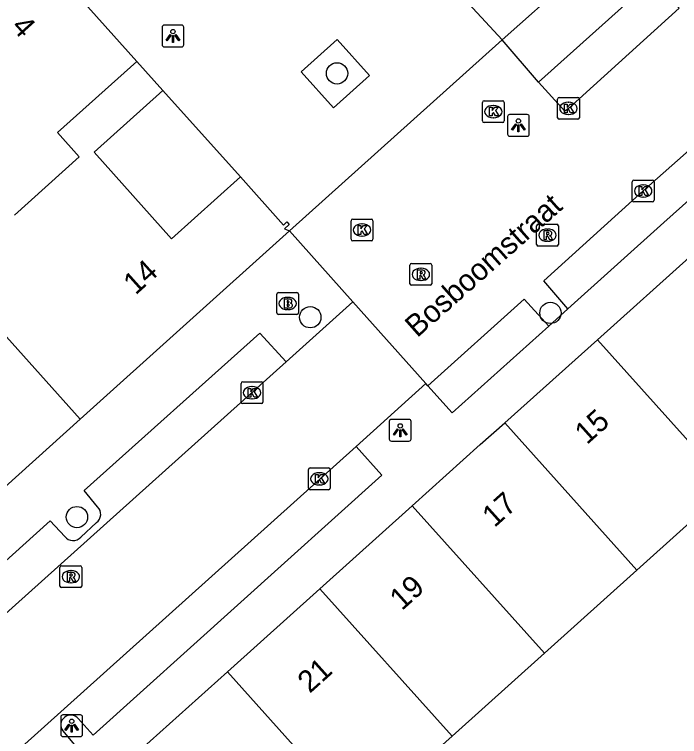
# Model space of a CAD drawing. Extents: x 162172 to 163187, y 382874 to 383684.
# Drawn here: x 162844.4 to 162874.91, y 383502.39 to 383535.51 of the extents above; entities that cross this region are included whole.
import ezdxf

# ---------------------------------------------------------------- set-up
doc = ezdxf.new("R2010")
doc.units = 0
for name, color, linetype in [('IMGEO_Boom', 7, 'Continuous'), ('IMGEO_Brandkraan', 7, 'Continuous'), ('IMGEO_Kolk', 7, 'Continuous'), ('IMGEO_Lichtpunt', 7, 'Continuous'), ('IMGEO_Muur', 7, 'Continuous'), ('IMGEO_Openbare_ruimte_label', 7, 'Continuous'), ('IMGEO_Pand', 7, 'Continuous'), ('IMGEO_Pand_nummerreeks', 7, 'Continuous'), ('IMGEO_Rijbaan_lokaal_open', 7, 'Continuous'), ('IMGEO_Rioolput', 7, 'Continuous'), ('IMGEO_Voetpad_open', 7, 'Continuous')]:
    doc.layers.add(name, color=color, linetype=linetype)

msp = doc.modelspace()

# ---------------------------------------------------------------- linework, layer by layer
at = {"layer": 'IMGEO_Boom'}
for centre in [(162859.201, 383532.804), (162868.991, 383521.821), (162857.974, 383521.623), (162847.27, 383512.456)]:
    msp.add_circle(centre, 0.489, dxfattribs=at)
at = {"layer": 'IMGEO_Brandkraan'}
for p, q in [((162856.435, 383521.824), (162856.435, 383522.676)), ((162856.51, 383522.75), (162857.362, 383522.75)), ((162856.923, 383522.53), (162856.948, 383522.53)), ((162857.436, 383522.676), (162857.436, 383521.824)), ((162856.946, 383521.97), (162856.921, 383521.97)), ((162857.362, 383521.75), (162856.51, 383521.75))]:
    msp.add_line(p, q, dxfattribs=at)
for points in [[(162856.435, 383521.824), (162856.435, 383522.676)], [(162856.51, 383522.75), (162857.362, 383522.75)], [(162857.436, 383522.676), (162857.436, 383521.824)], [(162856.783, 383522.45), (162856.783, 383522.05), (162856.996, 383522.05)], [(162857.014, 383522.45), (162856.783, 383522.45)], [(162856.962, 383522.369), (162856.908, 383522.369), (162856.908, 383522.293)], [(162856.908, 383522.293), (162856.961, 383522.293)], [(162856.97, 383522.217), (162856.908, 383522.217), (162856.908, 383522.136)], [(162856.908, 383522.136), (162856.97, 383522.136)], [(162857.362, 383521.75), (162856.51, 383521.75)]]:
    msp.add_lwpolyline(points, dxfattribs=at)
for centre, radius, start, end in [((162856.512, 383522.674), 0.0765, 91.552, 178.448), ((162856.512, 383522.674), 0.0765, 91.552, 178.448), ((162857.36, 383522.674), 0.0765, 1.552, 88.448), ((162857.36, 383522.674), 0.0765, 1.552, 88.448), ((162856.963, 383522.331), 0.0379, 267.8285, 90.9355), ((162856.971, 383522.176), 0.0404, 269.8759, 90.5077), ((162857.018, 383522.305), 0.145, 59.4692, 91.5367), ((162857.043, 383522.352), 0.0922, 285.5137, 58.1501), ((162857.048, 383522.16), 0.105, 301.3115, 78.989), ((162856.512, 383521.826), 0.0765, 181.552, 268.448), ((162856.512, 383521.826), 0.0765, 181.552, 268.448), ((162857.002, 383522.301), 0.251, 268.6676, 293.5347), ((162857.36, 383521.826), 0.0765, 271.552, 358.448), ((162857.36, 383521.826), 0.0765, 271.552, 358.448)]:
    msp.add_arc(centre, radius, start, end, dxfattribs=at)
for centre, major_axis, ratio, start_param, end_param in [((162856.922, 383522.25), (-0.387, 0.002), 0.722429, 4.712389, 7.853982), ((162856.947, 383522.25), (-0.39, 0.002), 0.717154, 1.570796, 4.712389)]:
    msp.add_ellipse(centre, major_axis=major_axis, ratio=ratio, start_param=start_param, end_param=end_param, dxfattribs=at)
at = {"layer": 'IMGEO_Kolk'}
for p, q in [((162865.872, 383530.623), (162865.872, 383531.475)), ((162865.947, 383531.549), (162866.799, 383531.549)), ((162866.873, 383531.475), (162866.873, 383530.623)), ((162869.315, 383530.771), (162869.315, 383531.623)), ((162869.39, 383531.697), (162870.242, 383531.697)), ((162869.803, 383531.477), (162869.828, 383531.477)), ((162870.316, 383531.623), (162870.316, 383530.771)), ((162866.36, 383531.329), (162866.385, 383531.329)), ((162866.383, 383530.769), (162866.358, 383530.769)), ((162869.826, 383530.917), (162869.801, 383530.917)), ((162866.799, 383530.549), (162865.947, 383530.549)), ((162870.242, 383530.697), (162869.39, 383530.697)), ((162872.746, 383526.984), (162872.746, 383527.836)), ((162872.821, 383527.91), (162873.673, 383527.91)), ((162873.747, 383527.836), (162873.747, 383526.984)), ((162873.234, 383527.69), (162873.259, 383527.69)), ((162873.257, 383527.13), (162873.232, 383527.13)), ((162873.673, 383526.91), (162872.821, 383526.91)), ((162859.849, 383525.195), (162859.849, 383526.047)), ((162859.924, 383526.121), (162860.776, 383526.121)), ((162860.337, 383525.901), (162860.362, 383525.901)), ((162860.85, 383526.047), (162860.85, 383525.195)), ((162860.36, 383525.341), (162860.335, 383525.341)), ((162860.776, 383525.121), (162859.924, 383525.121)), ((162854.803, 383517.733), (162854.803, 383518.585)), ((162854.878, 383518.659), (162855.73, 383518.659)), ((162855.804, 383518.585), (162855.804, 383517.733)), ((162855.291, 383518.439), (162855.316, 383518.439)), ((162855.314, 383517.879), (162855.289, 383517.879)), ((162855.73, 383517.659), (162854.878, 383517.659)), ((162857.889, 383513.785), (162857.889, 383514.637)), ((162857.964, 383514.711), (162858.816, 383514.711)), ((162858.89, 383514.637), (162858.89, 383513.785)), ((162858.377, 383514.491), (162858.402, 383514.491)), ((162858.4, 383513.931), (162858.375, 383513.931)), ((162858.816, 383513.711), (162857.964, 383513.711))]:
    msp.add_line(p, q, dxfattribs=at)
for points in [[(162865.872, 383530.623), (162865.872, 383531.475)], [(162865.947, 383531.549), (162866.799, 383531.549)], [(162866.873, 383531.475), (162866.873, 383530.623)], [(162869.315, 383530.771), (162869.315, 383531.623)], [(162869.39, 383531.697), (162870.242, 383531.697)], [(162870.316, 383531.623), (162870.316, 383530.771)], [(162866.193, 383531.249), (162866.316, 383531.249), (162866.316, 383531.098), (162866.446, 383531.249), (162866.61, 383531.249), (162866.464, 383531.098), (162866.617, 383530.849), (162866.465, 383530.849), (162866.38, 383531.013), (162866.316, 383530.946), (162866.316, 383530.849), (162866.193, 383530.849), (162866.193, 383531.249)], [(162869.636, 383531.397), (162869.759, 383531.397), (162869.759, 383531.246), (162869.889, 383531.397), (162870.053, 383531.397), (162869.907, 383531.246), (162870.06, 383530.997), (162869.908, 383530.997), (162869.823, 383531.161), (162869.759, 383531.094), (162869.759, 383530.997), (162869.636, 383530.997), (162869.636, 383531.397)], [(162866.799, 383530.549), (162865.947, 383530.549)], [(162870.242, 383530.697), (162869.39, 383530.697)], [(162872.746, 383526.984), (162872.746, 383527.836)], [(162872.821, 383527.91), (162873.673, 383527.91)], [(162873.747, 383527.836), (162873.747, 383526.984)], [(162873.067, 383527.61), (162873.19, 383527.61), (162873.19, 383527.459), (162873.32, 383527.61), (162873.484, 383527.61), (162873.338, 383527.459), (162873.491, 383527.21), (162873.339, 383527.21), (162873.254, 383527.374), (162873.19, 383527.307), (162873.19, 383527.21), (162873.067, 383527.21), (162873.067, 383527.61)], [(162873.673, 383526.91), (162872.821, 383526.91)], [(162859.849, 383525.195), (162859.849, 383526.047)], [(162859.924, 383526.121), (162860.776, 383526.121)], [(162860.17, 383525.821), (162860.293, 383525.821), (162860.293, 383525.67), (162860.423, 383525.821), (162860.587, 383525.821), (162860.441, 383525.67), (162860.594, 383525.421), (162860.442, 383525.421), (162860.357, 383525.585), (162860.293, 383525.518), (162860.293, 383525.421), (162860.17, 383525.421), (162860.17, 383525.821)], [(162860.85, 383526.047), (162860.85, 383525.195)], [(162860.776, 383525.121), (162859.924, 383525.121)], [(162854.803, 383517.733), (162854.803, 383518.585)], [(162854.878, 383518.659), (162855.73, 383518.659)], [(162855.804, 383518.585), (162855.804, 383517.733)], [(162855.124, 383518.359), (162855.247, 383518.359), (162855.247, 383518.208), (162855.377, 383518.359), (162855.541, 383518.359), (162855.395, 383518.208), (162855.548, 383517.959), (162855.396, 383517.959), (162855.311, 383518.123), (162855.247, 383518.056), (162855.247, 383517.959), (162855.124, 383517.959), (162855.124, 383518.359)], [(162855.73, 383517.659), (162854.878, 383517.659)], [(162857.889, 383513.785), (162857.889, 383514.637)], [(162857.964, 383514.711), (162858.816, 383514.711)], [(162858.89, 383514.637), (162858.89, 383513.785)], [(162858.21, 383514.411), (162858.333, 383514.411), (162858.333, 383514.26), (162858.463, 383514.411), (162858.627, 383514.411), (162858.481, 383514.26), (162858.634, 383514.011), (162858.482, 383514.011), (162858.397, 383514.175), (162858.333, 383514.108), (162858.333, 383514.011), (162858.21, 383514.011), (162858.21, 383514.411)], [(162858.816, 383513.711), (162857.964, 383513.711)]]:
    msp.add_lwpolyline(points, dxfattribs=at)
for centre, start, end in [((162865.949, 383531.473), 91.552, 178.448), ((162865.949, 383531.473), 91.552, 178.448), ((162866.797, 383531.473), 1.552, 88.448), ((162866.797, 383531.473), 1.552, 88.448), ((162869.392, 383531.621), 91.552, 178.448), ((162869.392, 383531.621), 91.552, 178.448), ((162870.24, 383531.621), 1.552, 88.448), ((162870.24, 383531.621), 1.552, 88.448), ((162869.392, 383530.773), 181.552, 268.448), ((162869.392, 383530.773), 181.552, 268.448), ((162870.24, 383530.773), 271.552, 358.448), ((162870.24, 383530.773), 271.552, 358.448), ((162865.949, 383530.625), 181.552, 268.448), ((162865.949, 383530.625), 181.552, 268.448), ((162866.797, 383530.625), 271.552, 358.448), ((162866.797, 383530.625), 271.552, 358.448), ((162872.823, 383527.834), 91.552, 178.448), ((162872.823, 383527.834), 91.552, 178.448), ((162873.671, 383527.834), 1.552, 88.448), ((162873.671, 383527.834), 1.552, 88.448), ((162872.823, 383526.986), 181.552, 268.448), ((162872.823, 383526.986), 181.552, 268.448), ((162873.671, 383526.986), 271.552, 358.448), ((162873.671, 383526.986), 271.552, 358.448), ((162859.926, 383526.045), 91.552, 178.448), ((162859.926, 383526.045), 91.552, 178.448), ((162860.774, 383526.045), 1.552, 88.448), ((162860.774, 383526.045), 1.552, 88.448), ((162859.926, 383525.197), 181.552, 268.448), ((162859.926, 383525.197), 181.552, 268.448), ((162860.774, 383525.197), 271.552, 358.448), ((162860.774, 383525.197), 271.552, 358.448), ((162854.88, 383518.583), 91.552, 178.448), ((162854.88, 383518.583), 91.552, 178.448), ((162855.728, 383518.583), 1.552, 88.448), ((162855.728, 383518.583), 1.552, 88.448), ((162854.88, 383517.735), 181.552, 268.448), ((162854.88, 383517.735), 181.552, 268.448), ((162855.728, 383517.735), 271.552, 358.448), ((162855.728, 383517.735), 271.552, 358.448), ((162857.966, 383514.635), 91.552, 178.448), ((162857.966, 383514.635), 91.552, 178.448), ((162858.814, 383514.635), 1.552, 88.448), ((162858.814, 383514.635), 1.552, 88.448), ((162857.966, 383513.787), 181.552, 268.448), ((162857.966, 383513.787), 181.552, 268.448), ((162858.814, 383513.787), 271.552, 358.448), ((162858.814, 383513.787), 271.552, 358.448)]:
    msp.add_arc(centre, 0.0765, start, end, dxfattribs=at)
for centre, major_axis, ratio, start_param, end_param in [((162869.802, 383531.197), (-0.387, 0.002), 0.722429, 4.712389, 7.853982), ((162869.827, 383531.197), (-0.39, 0.002), 0.717154, 1.570796, 4.712389), ((162866.359, 383531.049), (-0.387, 0.002), 0.722429, 4.712389, 7.853982), ((162866.384, 383531.049), (-0.39, 0.002), 0.717154, 1.570796, 4.712389), ((162873.233, 383527.41), (-0.387, 0.002), 0.722429, 4.712389, 7.853982), ((162873.258, 383527.41), (-0.39, 0.002), 0.717154, 1.570796, 4.712389), ((162860.336, 383525.621), (-0.387, 0.002), 0.722429, 4.712389, 7.853982), ((162860.361, 383525.621), (-0.39, 0.002), 0.717154, 1.570796, 4.712389), ((162855.29, 383518.159), (-0.387, 0.002), 0.722429, 4.712389, 7.853982), ((162855.315, 383518.159), (-0.39, 0.002), 0.717154, 1.570796, 4.712389), ((162858.376, 383514.211), (-0.387, 0.002), 0.722429, 4.712389, 7.853982), ((162858.401, 383514.211), (-0.39, 0.002), 0.717154, 1.570796, 4.712389)]:
    msp.add_ellipse(centre, major_axis=major_axis, ratio=ratio, start_param=start_param, end_param=end_param, dxfattribs=at)
at = {"layer": 'IMGEO_Lichtpunt'}
for p, q in [((162851.177, 383534.919), (162851.177, 383534.112)), ((162851.177, 383534.919), (162851.177, 383534.112)), ((162852.079, 383535.014), (162851.271, 383535.014)), ((162852.079, 383535.014), (162851.271, 383535.014)), ((162852.173, 383534.112), (162852.173, 383534.919)), ((162852.173, 383534.112), (162852.173, 383534.919)), ((162851.271, 383534.018), (162852.079, 383534.018)), ((162851.271, 383534.018), (162852.079, 383534.018)), ((162867.023, 383530.822), (162867.023, 383530.015)), ((162867.023, 383530.822), (162867.023, 383530.015)), ((162867.925, 383530.917), (162867.117, 383530.917)), ((162867.925, 383530.917), (162867.117, 383530.917)), ((162868.019, 383530.015), (162868.019, 383530.822)), ((162868.019, 383530.015), (162868.019, 383530.822)), ((162867.117, 383529.921), (162867.925, 383529.921)), ((162867.117, 383529.921), (162867.925, 383529.921)), ((162862.502, 383516.938), (162861.694, 383516.938)), ((162862.502, 383516.938), (162861.694, 383516.938)), ((162861.6, 383516.843), (162861.6, 383516.036)), ((162861.6, 383516.843), (162861.6, 383516.036)), ((162862.596, 383516.036), (162862.596, 383516.843)), ((162862.596, 383516.036), (162862.596, 383516.843)), ((162861.694, 383515.942), (162862.502, 383515.942)), ((162861.694, 383515.942), (162862.502, 383515.942)), ((162846.532, 383503.295), (162846.532, 383502.488)), ((162846.532, 383503.295), (162846.532, 383502.488)), ((162847.434, 383503.39), (162846.626, 383503.39)), ((162847.434, 383503.39), (162846.626, 383503.39)), ((162847.528, 383502.488), (162847.528, 383503.295)), ((162847.528, 383502.488), (162847.528, 383503.295)), ((162846.626, 383502.394), (162847.434, 383502.394)), ((162846.626, 383502.394), (162847.434, 383502.394))]:
    msp.add_line(p, q, dxfattribs=at)
for points in [[(162851.551, 383534.583), (162851.59, 383534.555), (162851.402, 383534.293), (162851.364, 383534.32), (162851.551, 383534.583)], [(162851.653, 383534.535), (162851.7, 383534.535), (162851.7, 383534.213), (162851.653, 383534.213), (162851.653, 383534.535)], [(162851.763, 383534.555), (162851.801, 383534.582), (162851.988, 383534.32), (162851.949, 383534.292), (162851.763, 383534.555)], [(162867.397, 383530.486), (162867.436, 383530.458), (162867.248, 383530.196), (162867.21, 383530.223), (162867.397, 383530.486)], [(162867.499, 383530.438), (162867.546, 383530.438), (162867.546, 383530.116), (162867.499, 383530.116), (162867.499, 383530.438)], [(162867.609, 383530.458), (162867.647, 383530.485), (162867.834, 383530.223), (162867.795, 383530.195), (162867.609, 383530.458)], [(162861.974, 383516.507), (162862.013, 383516.479), (162861.825, 383516.217), (162861.787, 383516.244), (162861.974, 383516.507)], [(162862.076, 383516.459), (162862.123, 383516.459), (162862.123, 383516.137), (162862.076, 383516.137), (162862.076, 383516.459)], [(162862.186, 383516.479), (162862.224, 383516.506), (162862.411, 383516.244), (162862.372, 383516.216), (162862.186, 383516.479)], [(162846.906, 383502.959), (162846.945, 383502.931), (162846.757, 383502.669), (162846.719, 383502.696), (162846.906, 383502.959)], [(162847.118, 383502.931), (162847.156, 383502.958), (162847.343, 383502.696), (162847.304, 383502.668), (162847.118, 383502.931)], [(162847.008, 383502.911), (162847.055, 383502.911), (162847.055, 383502.589), (162847.008, 383502.589), (162847.008, 383502.911)]]:
    msp.add_lwpolyline(points, dxfattribs=at)
for centre in [(162851.676, 383534.717), (162867.522, 383530.62), (162862.099, 383516.641), (162847.031, 383503.093)]:
    msp.add_circle(centre, 0.0994, dxfattribs=at)
for centre, start, end in [((162851.271, 383534.919), 90, 180), ((162851.271, 383534.919), 90, 180), ((162852.079, 383534.919), 0, 90), ((162852.079, 383534.919), 0, 90), ((162851.271, 383534.112), 180, 270), ((162851.271, 383534.112), 180, 270), ((162852.079, 383534.112), 270, 0), ((162852.079, 383534.112), 270, 360), ((162867.117, 383530.822), 90, 180), ((162867.117, 383530.822), 90, 180), ((162867.925, 383530.822), 0, 90), ((162867.925, 383530.822), 0, 90), ((162867.117, 383530.015), 180, 270), ((162867.117, 383530.015), 180, 270), ((162867.925, 383530.015), 270, 0), ((162867.925, 383530.015), 270, 360), ((162861.694, 383516.843), 90, 180), ((162861.694, 383516.843), 90, 180), ((162862.502, 383516.843), 0, 90), ((162862.502, 383516.843), 0, 90), ((162861.694, 383516.036), 180, 270), ((162861.694, 383516.036), 180, 270), ((162862.502, 383516.036), 270, 0), ((162862.502, 383516.036), 270, 360), ((162846.626, 383503.295), 90, 180), ((162846.626, 383503.295), 90, 180), ((162847.434, 383503.295), 0, 90), ((162847.434, 383503.295), 0, 90), ((162846.626, 383502.488), 180, 270), ((162846.626, 383502.488), 180, 270), ((162847.434, 383502.488), 270, 0), ((162847.434, 383502.488), 270, 360)]:
    msp.add_arc(centre, 0.0946, start, end, dxfattribs=at)
at = {"layer": 'IMGEO_Muur'}
msp.add_lwpolyline([(162869.874, 383537.103), (162866.772, 383534.334)], dxfattribs=at)
at = {"layer": 'IMGEO_Pand'}
for points in [[(162843.665, 383540.436), (162850.017, 383533.352)], [(162844.404, 383526.297), (162847.381, 383528.97), (162846.379, 383530.086), (162850.017, 383533.352)], [(162850.017, 383533.352), (162851.213, 383532.018)], [(162854.768, 383528.052), (162851.61, 383525.222), (162848.057, 383529.187), (162851.213, 383532.018)], [(162854.768, 383528.052), (162856.741, 383525.85), (162856.906, 383525.99), (162857.01, 383525.875), (162856.795, 383525.68), (162857.018, 383525.576)], [(162871.143, 383520.586), (162875.503, 383524.493), (162877.143, 383525.963)], [(162857.018, 383525.576), (162847.425, 383516.946)], [(162847.425, 383516.946), (162841.428, 383523.625)], [(162866.898, 383516.782), (162871.143, 383520.586)], [(162877.201, 383513.839), (162871.143, 383520.586)], [(162847.425, 383516.946), (162843.186, 383513.136)], [(162862.655, 383512.976), (162865.77, 383515.789), (162866.898, 383516.782)], [(162866.898, 383516.782), (162872.96, 383510.031)], [(162877.201, 383513.839), (162872.96, 383510.031)], [(162858.412, 383509.17), (162862.655, 383512.976)], [(162862.655, 383512.976), (162868.718, 383506.222)], [(162872.96, 383510.031), (162868.718, 383506.222)], [(162854.17, 383505.363), (162858.412, 383509.17)], [(162864.477, 383502.415), (162858.412, 383509.17)], [(162868.718, 383506.222), (162864.477, 383502.415)], [(162849.743, 383501.392), (162854.17, 383505.363)], [(162854.17, 383505.363), (162860.236, 383498.607)], [(162864.477, 383502.415), (162860.236, 383498.607)]]:
    msp.add_lwpolyline(points, dxfattribs=at)
at = {"layer": 'IMGEO_Rijbaan_lokaal_open'}
for points in [[(162866.772, 383534.334), (162862.933, 383538.493)], [(162873.7, 383537.121), (162874.892, 383535.799), (162869.816, 383531.197), (162869.645, 383531.072), (162868.447, 383532.394)], [(162857.018, 383525.576), (162866.772, 383534.334)], [(162859.211, 383534.36), (162857.56, 383532.881), (162859.04, 383531.229), (162860.691, 383532.708), (162859.211, 383534.36)], [(162868.447, 383532.394), (162866.772, 383534.334)], [(162851.213, 383532.018), (162854.768, 383528.052)], [(162869.794, 383522.011), (162868.687, 383523.285), (162873.247, 383527.41), (162878.359, 383531.942), (162879.489, 383530.695)], [(162859.927, 383522.332), (162857.018, 383525.576)], [(162856.866, 383519.569), (162859.927, 383522.332)], [(162859.927, 383522.332), (162863.277, 383518.589)], [(162863.359, 383518.483), (162867.789, 383522.45), (162868.92, 383521.21)], [(162869.794, 383522.011), (162868.92, 383521.21)], [(162833.213, 383498.368), (162856.866, 383519.569)], [(162863.277, 383518.589), (162860.073, 383515.696)], [(162863.359, 383518.483), (162863.277, 383518.589)], [(162815.972, 383476.091), (162860.073, 383515.696)]]:
    msp.add_lwpolyline(points, dxfattribs=at)
at = {"layer": 'IMGEO_Rioolput'}
for p, q in [((162868.354, 383524.957), (162868.354, 383525.809)), ((162868.429, 383525.883), (162869.281, 383525.883)), ((162869.355, 383525.809), (162869.355, 383524.957)), ((162868.842, 383525.663), (162868.867, 383525.663)), ((162869.281, 383524.883), (162868.429, 383524.883)), ((162868.865, 383525.103), (162868.84, 383525.103)), ((162862.547, 383523.159), (162862.547, 383524.011)), ((162862.622, 383524.085), (162863.474, 383524.085)), ((162863.035, 383523.865), (162863.06, 383523.865)), ((162863.548, 383524.011), (162863.548, 383523.159)), ((162863.058, 383523.305), (162863.033, 383523.305)), ((162863.474, 383523.085), (162862.622, 383523.085)), ((162846.492, 383509.296), (162846.492, 383510.148)), ((162846.567, 383510.222), (162847.419, 383510.222)), ((162846.98, 383510.002), (162847.005, 383510.002)), ((162847.493, 383510.148), (162847.493, 383509.296)), ((162847.003, 383509.442), (162846.978, 383509.442)), ((162847.419, 383509.222), (162846.567, 383509.222))]:
    msp.add_line(p, q, dxfattribs=at)
for points in [[(162868.354, 383524.957), (162868.354, 383525.809)], [(162868.429, 383525.883), (162869.281, 383525.883)], [(162869.355, 383525.809), (162869.355, 383524.957)], [(162868.943, 383525.581), (162868.691, 383525.583), (162868.691, 383525.183)], [(162868.869, 383525.502), (162868.815, 383525.502), (162868.815, 383525.421)], [(162868.691, 383525.183), (162868.815, 383525.183), (162868.815, 383525.345), (162868.826, 383525.345)], [(162868.815, 383525.421), (162868.867, 383525.421)], [(162868.873, 383525.316), (162868.944, 383525.183), (162869.084, 383525.183), (162869.019, 383525.309)], [(162869.281, 383524.883), (162868.429, 383524.883)], [(162862.547, 383523.159), (162862.547, 383524.011)], [(162862.622, 383524.085), (162863.474, 383524.085)], [(162863.548, 383524.011), (162863.548, 383523.159)], [(162863.136, 383523.783), (162862.884, 383523.785), (162862.884, 383523.385)], [(162862.884, 383523.385), (162863.008, 383523.385), (162863.008, 383523.547), (162863.019, 383523.547)], [(162863.062, 383523.704), (162863.008, 383523.704), (162863.008, 383523.623)], [(162863.008, 383523.623), (162863.06, 383523.623)], [(162863.066, 383523.518), (162863.137, 383523.385), (162863.277, 383523.385), (162863.212, 383523.511)], [(162863.474, 383523.085), (162862.622, 383523.085)], [(162846.492, 383509.296), (162846.492, 383510.148)], [(162846.567, 383510.222), (162847.419, 383510.222)], [(162847.081, 383509.92), (162846.829, 383509.922), (162846.829, 383509.522)], [(162847.493, 383510.148), (162847.493, 383509.296)], [(162846.829, 383509.522), (162846.953, 383509.522), (162846.953, 383509.684), (162846.964, 383509.684)], [(162847.007, 383509.841), (162846.953, 383509.841), (162846.953, 383509.76)], [(162846.953, 383509.76), (162847.005, 383509.76)], [(162847.011, 383509.655), (162847.082, 383509.522), (162847.222, 383509.522), (162847.157, 383509.648)], [(162847.419, 383509.222), (162846.567, 383509.222)]]:
    msp.add_lwpolyline(points, dxfattribs=at)
for centre, radius, start, end in [((162868.431, 383525.807), 0.0765, 91.552, 178.448), ((162868.431, 383525.807), 0.0765, 91.552, 178.448), ((162869.279, 383525.807), 0.0765, 1.552, 88.448), ((162869.279, 383525.807), 0.0765, 1.552, 88.448), ((162868.875, 383525.406), 0.0964, 77.0061, 93.1865), ((162868.889, 383525.463), 0.0378, 276.6634, 79.6772), ((162868.942, 383525.471), 0.109, 350.3612, 89.416), ((162868.825, 383525.292), 0.0533, 26.0293, 88.6989), ((162868.851, 383525.61), 0.19, 274.7715, 282.9687), ((162868.94, 383525.471), 0.112, 277.5842, 350.9817), ((162868.924, 383525.256), 0.108, 29.5134, 73.7905), ((162868.431, 383524.959), 0.0765, 181.552, 268.448), ((162868.431, 383524.959), 0.0765, 181.552, 268.448), ((162869.279, 383524.959), 0.0765, 271.552, 358.448), ((162869.279, 383524.959), 0.0765, 271.552, 358.448), ((162862.624, 383524.009), 0.0765, 91.552, 178.448), ((162862.624, 383524.009), 0.0765, 91.552, 178.448), ((162863.472, 383524.009), 0.0765, 1.552, 88.448), ((162863.472, 383524.009), 0.0765, 1.552, 88.448), ((162863.018, 383523.494), 0.0533, 26.0293, 88.6989), ((162863.044, 383523.812), 0.19, 274.7715, 282.9687), ((162863.068, 383523.608), 0.0964, 77.0061, 93.1865), ((162863.082, 383523.665), 0.0378, 276.6634, 79.6772), ((162863.135, 383523.673), 0.109, 350.3612, 89.416), ((162863.133, 383523.673), 0.112, 277.5842, 350.9817), ((162863.117, 383523.458), 0.108, 29.5134, 73.7905), ((162862.624, 383523.161), 0.0765, 181.552, 268.448), ((162862.624, 383523.161), 0.0765, 181.552, 268.448), ((162863.472, 383523.161), 0.0765, 271.552, 358.448), ((162863.472, 383523.161), 0.0765, 271.552, 358.448), ((162846.569, 383510.146), 0.0765, 91.552, 178.448), ((162846.569, 383510.146), 0.0765, 91.552, 178.448), ((162847.08, 383509.81), 0.109, 350.3612, 89.416), ((162847.417, 383510.146), 0.0765, 1.552, 88.448), ((162847.417, 383510.146), 0.0765, 1.552, 88.448), ((162846.963, 383509.631), 0.0533, 26.0293, 88.6989), ((162846.989, 383509.949), 0.19, 274.7715, 282.9687), ((162847.013, 383509.745), 0.0964, 77.0061, 93.1865), ((162847.027, 383509.802), 0.0378, 276.6634, 79.6772), ((162847.078, 383509.81), 0.112, 277.5842, 350.9817), ((162847.062, 383509.595), 0.108, 29.5134, 73.7905), ((162846.569, 383509.298), 0.0765, 181.552, 268.448), ((162846.569, 383509.298), 0.0765, 181.552, 268.448), ((162847.417, 383509.298), 0.0765, 271.552, 358.448), ((162847.417, 383509.298), 0.0765, 271.552, 358.448)]:
    msp.add_arc(centre, radius, start, end, dxfattribs=at)
for centre, major_axis, ratio, start_param, end_param in [((162868.841, 383525.383), (-0.387, 0.002), 0.722429, 4.712389, 7.853982), ((162868.866, 383525.383), (-0.39, 0.002), 0.717154, 1.570796, 4.712389), ((162863.034, 383523.585), (-0.387, 0.002), 0.722429, 4.712389, 7.853982), ((162863.059, 383523.585), (-0.39, 0.002), 0.717154, 1.570796, 4.712389), ((162846.979, 383509.722), (-0.387, 0.002), 0.722429, 4.712389, 7.853982), ((162847.004, 383509.722), (-0.39, 0.002), 0.717154, 1.570796, 4.712389)]:
    msp.add_ellipse(centre, major_axis=major_axis, ratio=ratio, start_param=start_param, end_param=end_param, dxfattribs=at)
at = {"layer": 'IMGEO_Voetpad_open'}
for points in [[(162869.874, 383537.103), (162866.772, 383534.334)], [(162873.7, 383537.121), (162868.447, 383532.394)], [(162879.489, 383530.695), (162874.196, 383525.966), (162869.794, 383522.011)], [(162868.92, 383521.21), (162864.477, 383517.233), (162863.359, 383518.483)], [(162848.22, 383512.921), (162847.597, 383513.678), (162855.661, 383520.889), (162856.866, 383519.569)], [(162860.073, 383515.696), (162861.252, 383514.384), (162848.016, 383502.465), (162847.328, 383503.221)], [(162833.213, 383498.368), (162832.049, 383499.676), (162846.044, 383512.284), (162846.714, 383511.569)], [(162847.446, 383511.538), (162848.17, 383512.208)], [(162846.62, 383502.649), (162847.298, 383501.852), (162831.068, 383487.264), (162830.407, 383488.023)]]:
    msp.add_lwpolyline(points, dxfattribs=at)
for centre, radius, start, end in [((162847.89, 383512.586), 0.471, 306.5811, 45.3961), ((162847.093, 383511.858), 0.477, 217.3642, 317.7858), ((162846.985, 383502.921), 0.455, 41.2208, 216.6493)]:
    msp.add_arc(centre, radius, start, end, dxfattribs=at)

# ---------------------------------------------------------------- texts
at = {"layer": 'IMGEO_Openbare_ruimte_label'}
msp.add_text('Bosboomstraat', height=1, rotation=41.5526, dxfattribs=at).set_placement((162862.875, 383520.656))
at = {"layer": 'IMGEO_Pand_nummerreeks'}
for s, rotation, p in [('4', 311.8843, (162844.216, 383534.91)), ('14', 41.9498, (162849.958, 383522.61)), ('15', 41.8634, (162870.662, 383515.751)), ('17', 41.8893, (162866.419, 383511.946)), ('19', 41.8996, (162862.176, 383508.141)), ('21', 41.8996, (162857.95, 383504.349))]:
    msp.add_text(s, height=1, rotation=rotation, dxfattribs=at).set_placement(p)

doc.saveas('drawing.dxf')
